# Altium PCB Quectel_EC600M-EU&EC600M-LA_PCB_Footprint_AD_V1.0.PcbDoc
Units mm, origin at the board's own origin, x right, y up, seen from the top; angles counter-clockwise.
Board outline 152.4 x 101.6 mm, 2 copper layers (Top Layer, Bottom Layer); 1 components, 0 nets, 106 pads, 0 vias.
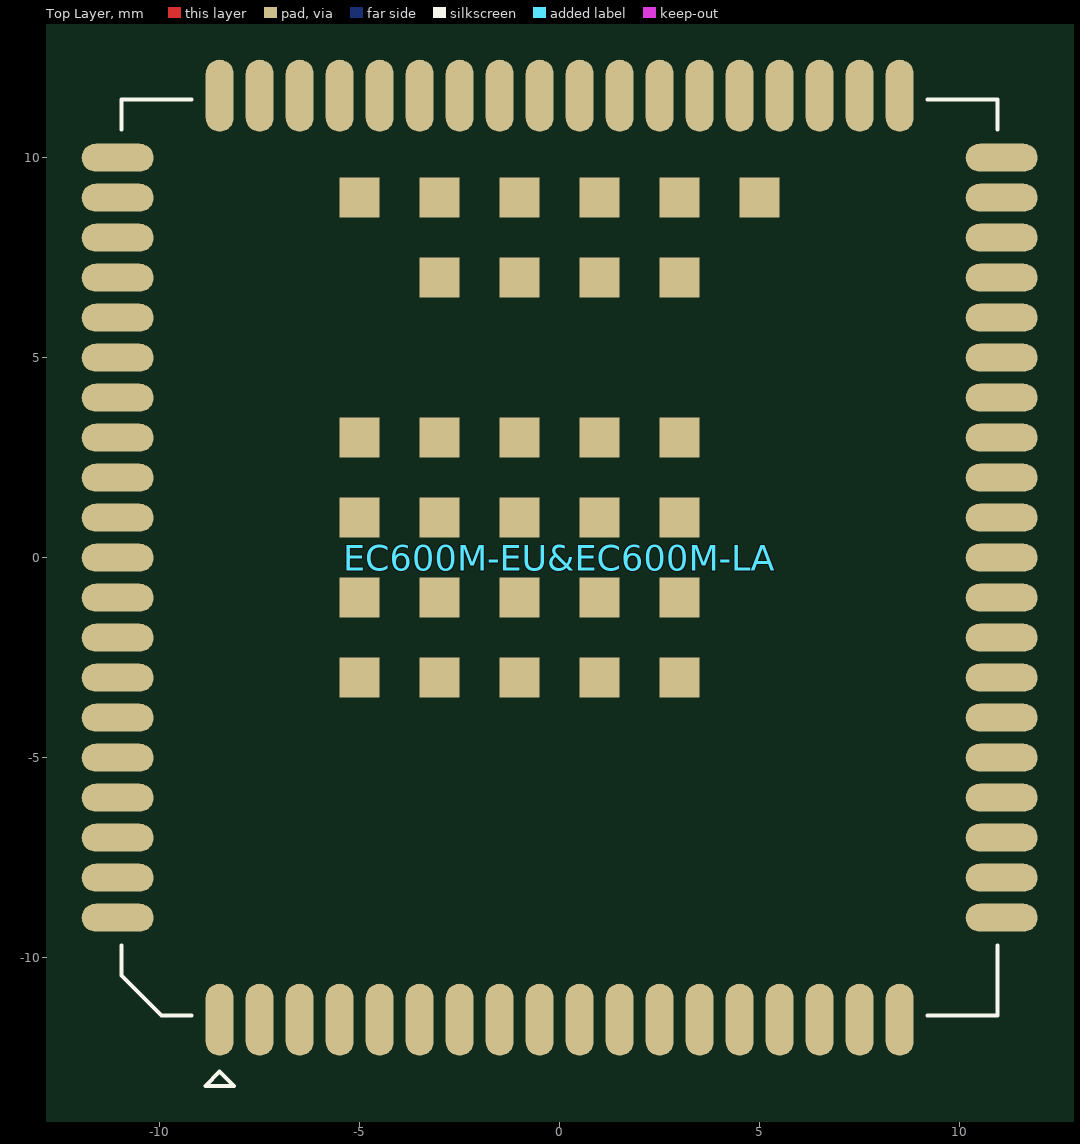
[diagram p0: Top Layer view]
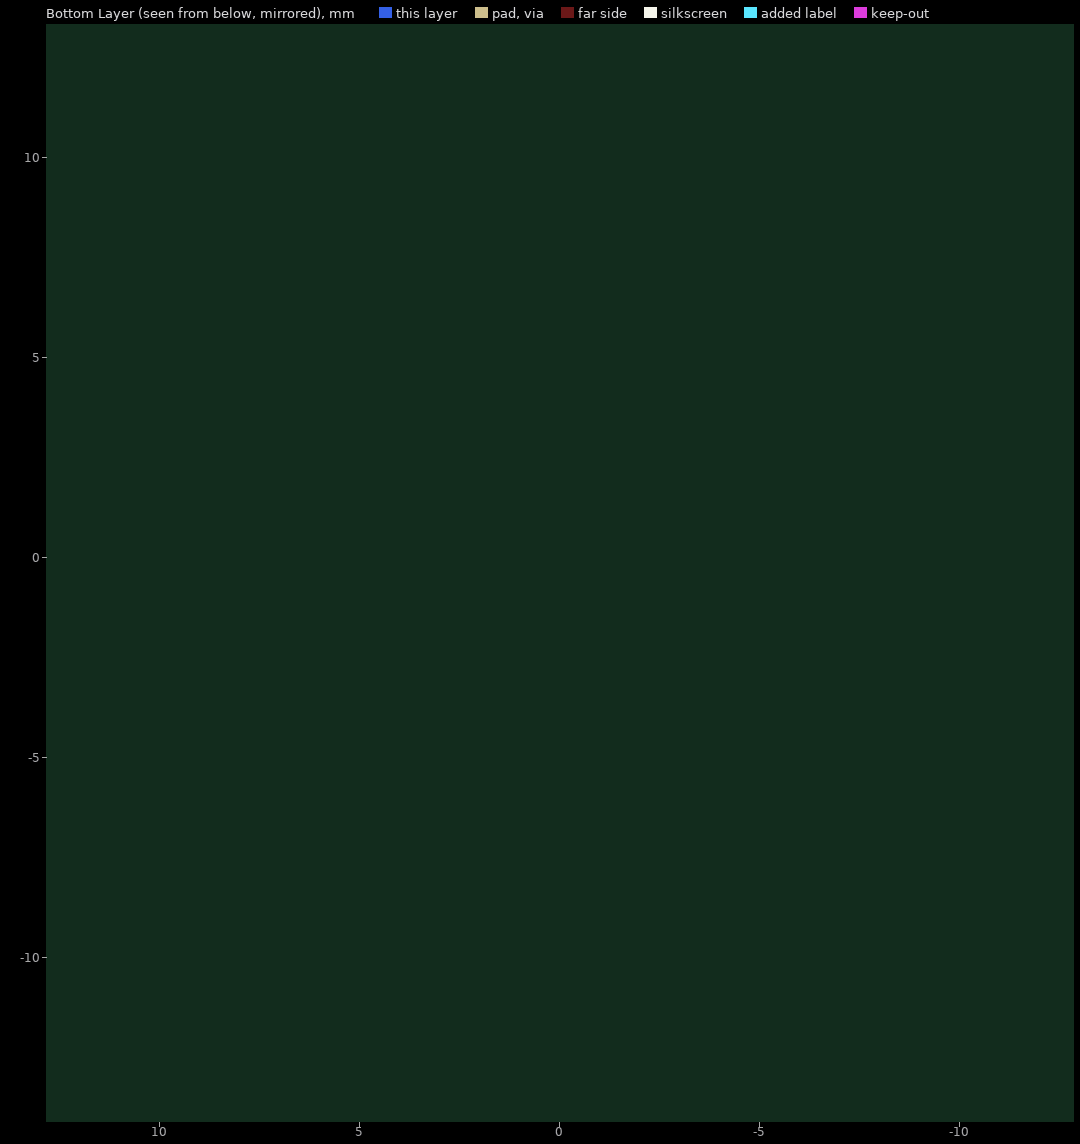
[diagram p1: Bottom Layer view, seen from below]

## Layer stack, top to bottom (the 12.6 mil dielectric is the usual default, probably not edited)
Top Solder: solder mask 0.0102, Solder Resist, Dk 3.5
Top Layer: signal copper 0.0356
Dielectric1: dielectric 0.32, FR-4, Dk 4.8
Bottom Layer: signal copper 0.0356
Bottom Solder: solder mask 0.0102, Solder Resist, Dk 3.5

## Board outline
-70.739,-53.721 81.661,-53.721 81.661,47.879 -70.739,47.879

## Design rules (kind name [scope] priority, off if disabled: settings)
Clearance [All] p1: gap=0.254 ignorepadtopadclearanceinfootprint=FALSE except(0: Arc-Hole Track-Hole SMDPad-Hole THPad-Hole Via-Hole Fill-Hole Poly-Hole Region-Hole Text-Hole)
PolygonConnect [All] p1: connectstyle=Relief reliefconductorwidth=0.254 reliefentries=4 polygonreliefangle="90 Angle" airgapwidth=0.254
RoutingVias [All] p1: holewidth=0.711 width=1.27 viastyle="Through Hole" minholewidth=0.711 minwidth=1.27 maxholewidth=0.711 maxwidth=1.27
SolderMaskExpansion [All] p1: expansion=0.102 istentingtop=FALSE
Width [All] p1: maxlimit=0.254 minlimit=0.254 preferedwidth=0.254
30 further rules are at their usual default settings.

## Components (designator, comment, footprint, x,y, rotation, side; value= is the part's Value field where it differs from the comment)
EC600M-EU&EC600M-LA "Comment" EC600M-EU_EC600M-LA 0,0 r0 top

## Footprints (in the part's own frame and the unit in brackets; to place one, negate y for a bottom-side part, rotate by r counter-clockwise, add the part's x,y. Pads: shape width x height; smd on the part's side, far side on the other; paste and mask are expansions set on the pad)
EC600M-EU_EC600M-LA [mm] "EC600M-EU&EC600M-LA Module 106PIN 21.9x22.9mm H2.4mm RO"
  oval 0.7x1.8 smd mask+0.05: 1(-8.5,-11.55) 2(-7.5,-11.55) 3(-6.5,-11.55) 4(-5.5,-11.55) 5(-4.5,-11.55) 6(-3.5,-11.55) 7(-2.5,-11.55) 8(-1.5,-11.55) 9(-0.5,-11.55) 10(0.5,-11.55) 11(1.5,-11.55) 12(2.5,-11.55) 13(3.5,-11.55) 14(4.5,-11.55) 15(5.5,-11.55) 16(6.5,-11.55) 17(7.5,-11.55) 18(8.5,-11.55) 39(8.5,11.55) 40(7.5,11.55) 41(6.5,11.55) 42(5.5,11.55) 43(4.5,11.55) 44(3.5,11.55) 45(2.5,11.55) 46(1.5,11.55) 47(0.5,11.55) 48(-0.5,11.55) 49(-1.5,11.55) 50(-2.5,11.55) 51(-3.5,11.55) 52(-4.5,11.55) 53(-5.5,11.55) 54(-6.5,11.55) 55(-7.5,11.55) 56(-8.5,11.55)
  oval 1.8x0.7 smd mask+0.05: 19(11.05,-9) 20(11.05,-8) 21(11.05,-7) 22(11.05,-6) 23(11.05,-5) 24(11.05,-4) 25(11.05,-3) 26(11.05,-2) 27(11.05,-1) 28(11.05,0) 29(11.05,1) 30(11.05,2) 31(11.05,3) 32(11.05,4) 33(11.05,5) 34(11.05,6) 35(11.05,7) 36(11.05,8) 37(11.05,9) 38(11.05,10) 57(-11.05,10) 58(-11.05,9) 59(-11.05,8) 60(-11.05,7) 61(-11.05,6) 62(-11.05,5) 63(-11.05,4) 64(-11.05,3) 65(-11.05,2) 66(-11.05,1) 67(-11.05,0) 68(-11.05,-1) 69(-11.05,-2) 70(-11.05,-3) 71(-11.05,-4) 72(-11.05,-5) 73(-11.05,-6) 74(-11.05,-7) 75(-11.05,-8) 76(-11.05,-9)
  rect 1x1 smd mask+0.05: 77(-3,-3) 78(-1,-3) 79(1,-3) 80(3,-3) 81(3,-1) 82(3,1) 83(3,3) 84(1,3) 85(-1,3) 86(-3,3) 87(-3,1) 88(-3,-1) 89(-1,-1) 90(1,-1) 91(1,1) 92(-1,1) 109(-5,3) 110(-5,1) 111(-5,-1) 112(-5,-3) 130(5,9) 131(3,9) 132(1,9) 133(-1,9) 134(-3,9) 135(-5,9) 145(3,7) 146(1,7) 147(-1,7) 148(-3,7)
  silkscreen extent -10.95,-13.2 10.95,11.45, body extent -10.96,-11.45 10.95,11.45, height 2.4

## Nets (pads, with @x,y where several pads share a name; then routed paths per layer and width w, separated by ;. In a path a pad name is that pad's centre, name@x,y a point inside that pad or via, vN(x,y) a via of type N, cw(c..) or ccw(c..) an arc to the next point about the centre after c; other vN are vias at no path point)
pads on no net: EC600M-EU&EC600M-LA.1 EC600M-EU&EC600M-LA.2 EC600M-EU&EC600M-LA.3 EC600M-EU&EC600M-LA.4 EC600M-EU&EC600M-LA.5 EC600M-EU&EC600M-LA.6 EC600M-EU&EC600M-LA.7 EC600M-EU&EC600M-LA.8 EC600M-EU&EC600M-LA.9 EC600M-EU&EC600M-LA.10 EC600M-EU&EC600M-LA.11 EC600M-EU&EC600M-LA.12 EC600M-EU&EC600M-LA.13 EC600M-EU&EC600M-LA.14 EC600M-EU&EC600M-LA.15 EC600M-EU&EC600M-LA.16 EC600M-EU&EC600M-LA.17 EC600M-EU&EC600M-LA.18 EC600M-EU&EC600M-LA.19 EC600M-EU&EC600M-LA.20 EC600M-EU&EC600M-LA.21 EC600M-EU&EC600M-LA.22 EC600M-EU&EC600M-LA.23 EC600M-EU&EC600M-LA.24 EC600M-EU&EC600M-LA.25 EC600M-EU&EC600M-LA.26 EC600M-EU&EC600M-LA.27 EC600M-EU&EC600M-LA.28 EC600M-EU&EC600M-LA.29 EC600M-EU&EC600M-LA.30 EC600M-EU&EC600M-LA.31 EC600M-EU&EC600M-LA.32 EC600M-EU&EC600M-LA.33 EC600M-EU&EC600M-LA.34 EC600M-EU&EC600M-LA.35 EC600M-EU&EC600M-LA.36 EC600M-EU&EC600M-LA.37 EC600M-EU&EC600M-LA.38 EC600M-EU&EC600M-LA.39 EC600M-EU&EC600M-LA.40 EC600M-EU&EC600M-LA.41 EC600M-EU&EC600M-LA.42 EC600M-EU&EC600M-LA.43 EC600M-EU&EC600M-LA.44 EC600M-EU&EC600M-LA.45 EC600M-EU&EC600M-LA.46 EC600M-EU&EC600M-LA.47 EC600M-EU&EC600M-LA.48 EC600M-EU&EC600M-LA.49 EC600M-EU&EC600M-LA.50 EC600M-EU&EC600M-LA.51 EC600M-EU&EC600M-LA.52 EC600M-EU&EC600M-LA.53 EC600M-EU&EC600M-LA.54 EC600M-EU&EC600M-LA.55 EC600M-EU&EC600M-LA.56 EC600M-EU&EC600M-LA.57 EC600M-EU&EC600M-LA.58 EC600M-EU&EC600M-LA.59 EC600M-EU&EC600M-LA.60 EC600M-EU&EC600M-LA.61 EC600M-EU&EC600M-LA.62 EC600M-EU&EC600M-LA.63 EC600M-EU&EC600M-LA.64 EC600M-EU&EC600M-LA.65 EC600M-EU&EC600M-LA.66 EC600M-EU&EC600M-LA.67 EC600M-EU&EC600M-LA.68 EC600M-EU&EC600M-LA.69 EC600M-EU&EC600M-LA.70 EC600M-EU&EC600M-LA.71 EC600M-EU&EC600M-LA.72 EC600M-EU&EC600M-LA.73 EC600M-EU&EC600M-LA.74 EC600M-EU&EC600M-LA.75 EC600M-EU&EC600M-LA.76 EC600M-EU&EC600M-LA.77 EC600M-EU&EC600M-LA.78 EC600M-EU&EC600M-LA.79 EC600M-EU&EC600M-LA.80 EC600M-EU&EC600M-LA.81 EC600M-EU&EC600M-LA.82 EC600M-EU&EC600M-LA.83 EC600M-EU&EC600M-LA.84 EC600M-EU&EC600M-LA.85 EC600M-EU&EC600M-LA.86 EC600M-EU&EC600M-LA.87 EC600M-EU&EC600M-LA.88 EC600M-EU&EC600M-LA.89 EC600M-EU&EC600M-LA.90 EC600M-EU&EC600M-LA.91 EC600M-EU&EC600M-LA.92 EC600M-EU&EC600M-LA.109 EC600M-EU&EC600M-LA.110 EC600M-EU&EC600M-LA.111 EC600M-EU&EC600M-LA.112 EC600M-EU&EC600M-LA.130 EC600M-EU&EC600M-LA.131 EC600M-EU&EC600M-LA.132 EC600M-EU&EC600M-LA.133 EC600M-EU&EC600M-LA.134 EC600M-EU&EC600M-LA.135 EC600M-EU&EC600M-LA.145 EC600M-EU&EC600M-LA.146 EC600M-EU&EC600M-LA.147 EC600M-EU&EC600M-LA.148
